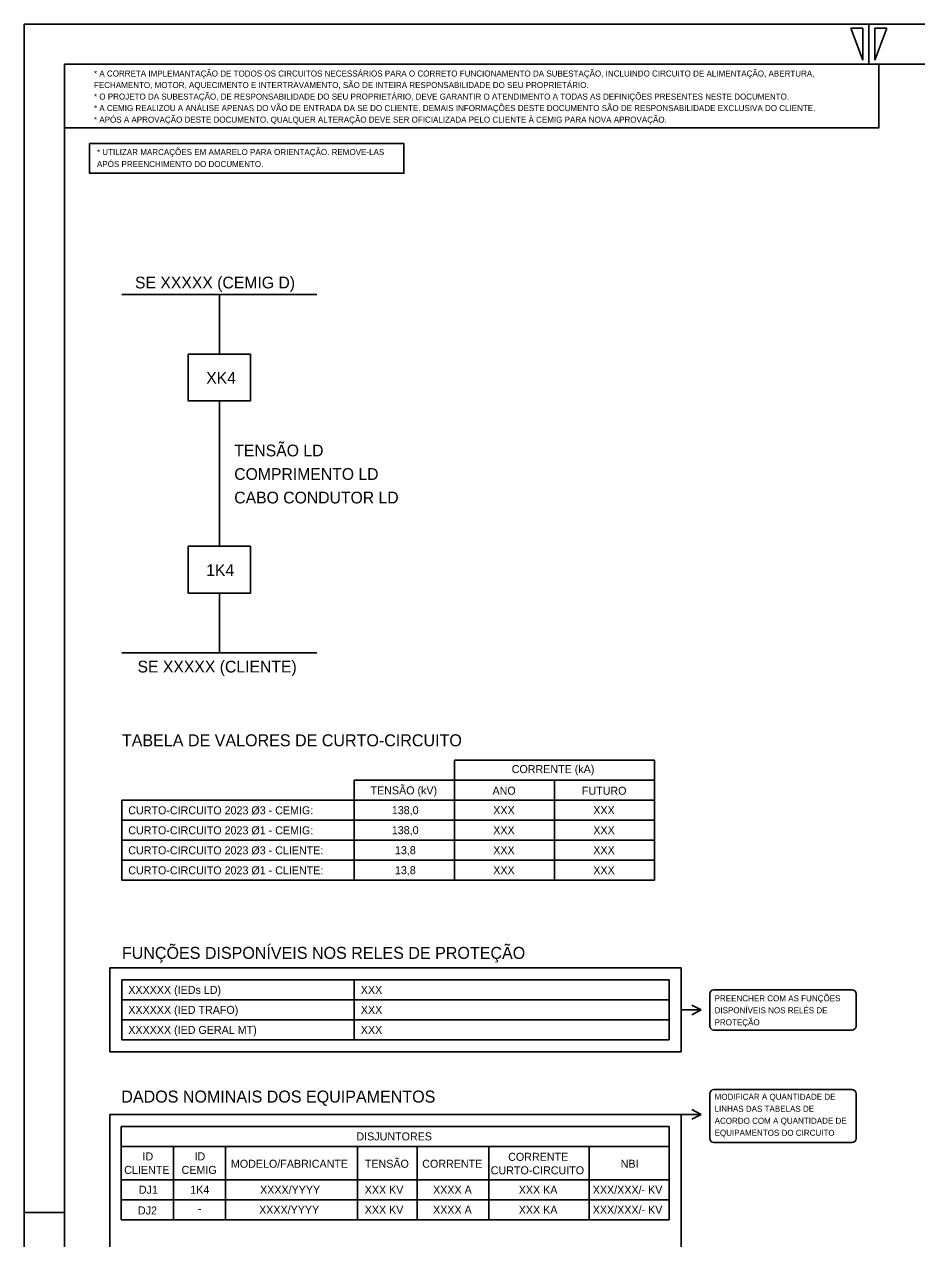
# Model space of a CAD drawing. Extents: x 563 to 1404, y 358 to 952.
# Drawn here: x 562.6 to 785.5, y 648.4 to 952 of the extents above; entities that cross this region are included whole.
import ezdxf

# ---------------------------------------------------------------- set-up
doc = ezdxf.new("R2010")
doc.units = 0
doc.layers.add('New Level (0)', color=7, linetype='Continuous')

# ---------------------------------------------------------------- blocks, each defined once
blk = doc.blocks.new('POINT_DISPLAY')
blk.add_line((0, 0), (0, 0))

msp = doc.modelspace()

# ---------------------------------------------------------------- linework, layer by layer
for p, q in [((586.96, 884.4), (635.66, 884.4)), ((611.31, 884.4), (611.31, 869.54)), ((611.31, 857.81), (611.31, 821.5)), ((611.31, 809.77), (611.31, 794.9)), ((586.96, 794.9), (635.66, 794.9))]:
    msp.add_line(p, q)
for points in [[(603.54, 869.54), (619.08, 869.54), (619.08, 857.81), (603.54, 857.81)], [(603.54, 821.5), (619.08, 821.5), (619.08, 809.77), (603.54, 809.77)]]:
    msp.add_lwpolyline(points, close=True)
at = {"layer": 'New Level (0)'}
for p, q in [((562.58, 951.96), (562.58, 357.96)), ((1403.58, 951.96), (562.58, 951.96)), ((1403.58, 951.96), (562.58, 951.96)), ((562.58, 951.96), (562.58, 357.96)), ((772.08, 950.96), (769.08, 950.96)), ((769.08, 950.96), (772.08, 942.96)), ((772.08, 942.96), (772.08, 950.96)), ((773.58, 951.96), (773.58, 941.96)), ((775.08, 942.96), (775.08, 950.96)), ((775.08, 950.96), (778.08, 950.96)), ((778.08, 950.96), (775.08, 942.96)), ((572.58, 941.96), (572.58, 367.96)), ((1393.58, 941.96), (572.58, 941.96)), ((572.58, 941.96), (572.58, 367.96)), ((670.01, 768.04), (670.01, 738.04)), ((670.01, 768.04), (720.01, 768.04)), ((720.01, 768.04), (720.01, 738.04)), ((645.01, 763.04), (645.01, 738.04)), ((645.01, 763.04), (720.01, 763.04)), ((695.01, 763.04), (695.01, 738.04)), ((586.96, 758.04), (720.01, 758.04)), ((586.96, 758.04), (586.96, 738.04)), ((586.96, 753.04), (720.01, 753.04)), ((586.96, 748.04), (720.01, 748.04)), ((586.96, 743.04), (720.01, 743.04)), ((586.96, 738.04), (720.01, 738.04)), ((583.96, 716.12), (583.96, 695.12)), ((583.96, 716.12), (726.65, 716.12)), ((726.65, 716.12), (726.65, 695.12)), ((586.96, 713.12), (723.65, 713.12)), ((586.96, 713.12), (586.96, 698.12)), ((586.96, 713.12), (586.96, 713.12)), ((586.96, 713.12), (586.96, 713.12)), ((645.01, 713.12), (645.01, 698.12)), ((723.65, 713.12), (723.65, 698.12)), ((734.84, 710.67), (742.19, 710.67)), ((742.19, 710.67), (769.38, 710.67)), ((586.96, 708.12), (723.65, 708.12)), ((733.84, 701.56), (733.84, 709.67)), ((770.38, 709.67), (770.38, 701.56)), ((726.65, 705.62), (731.68, 705.62)), ((731.68, 705.62), (729.38, 706.83)), ((731.68, 705.62), (729.38, 704.41)), ((586.96, 703.12), (723.65, 703.12)), ((586.96, 698.12), (723.65, 698.12)), ((769.38, 700.56), (734.84, 700.56)), ((583.96, 695.12), (726.65, 695.12)), ((733.84, 673.45), (733.84, 684.7)), ((734.84, 685.7), (742.19, 685.7)), ((742.19, 685.7), (769.38, 685.7)), ((770.38, 684.7), (770.38, 673.45)), ((731.68, 679.5), (729.38, 680.71)), ((583.96, 679.5), (726.65, 679.5)), ((583.96, 679.5), (583.96, 437.32)), ((726.65, 679.5), (731.68, 679.5)), ((726.65, 679.5), (726.65, 437.37)), ((731.68, 679.5), (729.38, 678.29)), ((586.81, 676.5), (586.81, 653.17)), ((586.81, 676.5), (723.65, 676.5)), ((723.65, 676.5), (723.65, 653.17)), ((723.65, 671.5), (586.81, 671.5)), ((599.81, 671.5), (599.81, 653.17)), ((612.81, 653.17), (612.81, 671.5)), ((645.81, 671.5), (645.81, 653.17)), ((660.72, 671.5), (660.72, 653.17)), ((678.66, 671.5), (678.66, 653.17)), ((703.66, 671.5), (703.66, 653.17)), ((769.38, 672.45), (734.84, 672.45)), ((586.81, 663.17), (723.65, 663.17)), ((586.81, 658.17), (723.65, 658.17)), ((562.58, 654.96), (572.58, 654.96)), ((586.81, 653.17), (723.65, 653.17)), ((586.81, 653.17), (586.81, 653.17))]:
    msp.add_line(p, q, dxfattribs=at)
for points in [[(572.58, 941.96), (776.08, 941.96), (776.08, 926.09), (572.58, 926.09)], [(578.87, 922.15), (657.43, 922.15), (657.43, 914.73), (578.87, 914.73)]]:
    msp.add_lwpolyline(points, close=True, dxfattribs=at)
for centre, start, end in [((734.84, 709.67), 90, 180), ((769.38, 709.67), 0, 90), ((734.84, 701.56), 180, 270), ((769.38, 701.56), 270, 0), ((734.84, 684.7), 90, 180), ((769.38, 684.7), 0, 90), ((734.84, 673.45), 180, 270), ((769.38, 673.45), 270, 0)]:
    msp.add_arc(centre, 1, start, end, dxfattribs=at)

# ---------------------------------------------------------------- block references
for p in [(670.01, 758.04), (670.01, 713.12), (655.23, 663.17)]:
    msp.add_blockref('POINT_DISPLAY', p, dxfattribs=at)

# ---------------------------------------------------------------- texts
for s, height, p in [('* UTILIZAR MARCAÇÕES EM AMARELO PARA ORIENTAÇÃO. REMOVE-LAS ', 1.5, (580.73, 919.27)), ('APÓS PREENCHIMENTO DO DOCUMENTO.', 1.5, (580.73, 916.27)), ('SE XXXXX (CEMIG D)', 2.94, (590.23, 885.94)), ('XK4', 2.94, (608.02, 862.11)), ('TENSÃO LD ', 2.94, (615.03, 843.96)), ('COMPRIMENTO LD', 2.94, (615.03, 838.08)), ('CABO CONDUTOR LD ', 2.94, (615.03, 832.2)), ('1K4', 2.94, (608.02, 814.07)), ('SE XXXXX (CLIENTE)', 2.94, (590.86, 789.95)), ('TABELA DE VALORES DE CURTO-CIRCUITO', 3, (586.96, 771.5)), ('CORRENTE (kA)', 2, (684.34, 764.81)), ('TENSÃO (kV)', 2, (649.07, 759.48)), ('ANO', 2, (679.54, 759.4)), ('FUTURO', 2, (701.87, 759.4)), ('CURTO-CIRCUITO 2023 Ø3 - CEMIG:', 2, (588.55, 754.5)), ('138,0', 2, (654.39, 754.54)), ('XXX', 2, (679.73, 754.54)), ('XXX', 2, (704.73, 754.54)), ('CURTO-CIRCUITO 2023 Ø1 - CEMIG:', 2, (588.55, 749.5)), ('138,0', 2, (654.39, 749.54)), ('XXX', 2, (679.73, 749.54)), ('XXX', 2, (704.73, 749.54)), ('CURTO-CIRCUITO 2023 Ø3 - CLIENTE:', 2, (588.55, 744.5)), ('13,8', 2, (655.16, 744.54)), ('XXX', 2, (679.73, 744.54)), ('XXX', 2, (704.73, 744.54)), ('CURTO-CIRCUITO 2023 Ø1 - CLIENTE:', 2, (588.55, 739.5)), ('13,8', 2, (655.16, 739.54)), ('XXX', 2, (679.73, 739.54)), ('XXX', 2, (704.73, 739.54)), ('FUNÇÕES DISPONÍVEIS NOS RELES DE PROTEÇÃO', 3, (586.96, 718.37)), ('XXXXXX (IEDs LD)', 2, (588.55, 709.62)), ('XXX', 2, (646.65, 709.62)), ('PREENCHER COM AS FUNÇÕES ', 1.5, (735.03, 707.77)), ('XXXXXX (IED TRAFO)', 2, (588.55, 704.62)), ('XXX', 2, (646.65, 704.62)), ('DISPONÍVEIS NOS RELÉS DE ', 1.5, (735.03, 704.77)), ('XXXXXX (IED GERAL MT)', 2, (588.55, 699.62)), ('XXX', 2, (646.65, 699.62)), ('PROTEÇÃO', 1.5, (735.03, 701.77)), ('DADOS NOMINAIS DOS EQUIPAMENTOS', 3, (586.81, 682.46)), ('MODIFICAR A QUANTIDADE DE ', 1.5, (735.03, 683.15)), ('LINHAS DAS TABELAS DE ', 1.5, (735.03, 680.15)), ('ACORDO COM A QUANTIDADE DE ', 1.5, (735.03, 677.15)), ('DISJUNTORES', 2, (645.55, 673)), ('EQUIPAMENTOS DO CIRCUITO', 1.5, (735.03, 674.15)), ('ID', 2, (592.1, 668)), ('ID', 2, (605.1, 668)), ('MODELO/FABRICANTE', 2, (614.19, 666.17)), ('TENSÃO', 2, (647.65, 666.17)), ('CORRENTE', 2, (661.99, 666.17)), ('CORRENTE', 2, (683.46, 667.9)), ('NBI', 2, (711.56, 666.17)), ('CLIENTE', 2, (587.54, 664.63)), ('CEMIG', 2, (601.87, 664.63)), ('CURTO-CIRCUITO', 2, (679.1, 664.53)), ('DJ1', 2, (591.19, 659.68)), ('XXXX/YYYY', 2, (621.48, 659.67)), ('XXX/XXX/- KV', 2, (704.59, 659.67)), ('1K4', 2, (604.05, 659.67)), ('XXX KV', 2, (647.62, 659.67)), ('XXXX A', 2, (664.7, 659.67)), ('XXX KA', 2, (686.11, 659.67)), ('DJ2', 2, (590.97, 654.49)), ('-', 2, (605.94, 654.95)), ('XXXX/YYYY', 2, (621.24, 654.67)), ('XXX KV', 2, (647.62, 654.67)), ('XXXX A', 2, (664.7, 654.67)), ('XXX KA', 2, (686.11, 654.67)), ('XXX/XXX/- KV', 2, (704.59, 654.67))]:
    msp.add_text(s, height=height).set_placement(p)
for s, p in [('* A CORRETA IMPLEMANTAÇÃO DE TODOS OS CIRCUITOS NECESSÁRIOS PARA O CORRETO FUNCIONAMENTO DA SUBESTAÇÃO, INCLUINDO CIRCUITO DE ALIMENTAÇÃO, ABERTURA,   ', (579.98, 938.9)), ('FECHAMENTO, MOTOR, AQUECIMENTO E INTERTRAVAMENTO, SÃO DE INTEIRA RESPONSABILIDADE DO SEU PROPRIETÁRIO.', (579.98, 936.02)), ('* O PROJETO DA SUBESTAÇÃO, DE RESPONSABILIDADE DO SEU PROPRIETÁRIO, DEVE GARANTIR O ATENDIMENTO A TODAS AS DEFINIÇÕES PRESENTES NESTE DOCUMENTO.', (579.98, 933.14)), ('* A CEMIG REALIZOU A ANÁLISE APENAS DO VÃO DE ENTRADA DA SE DO CLIENTE. DEMAIS INFORMAÇÕES DESTE DOCUMENTO SÃO DE RESPONSABILIDADE EXCLUSIVA DO CLIENTE.', (579.98, 930.26)), ('* APÓS A APROVAÇÃO DESTE DOCUMENTO, QUALQUER ALTERAÇÃO DEVE SER OFICIALIZADA PELO CLIENTE À CEMIG PARA NOVA APROVAÇÃO.', (579.98, 927.38))]:
    msp.add_text(s, height=1.5, dxfattribs=at).set_placement(p)

doc.saveas('drawing.dxf')
